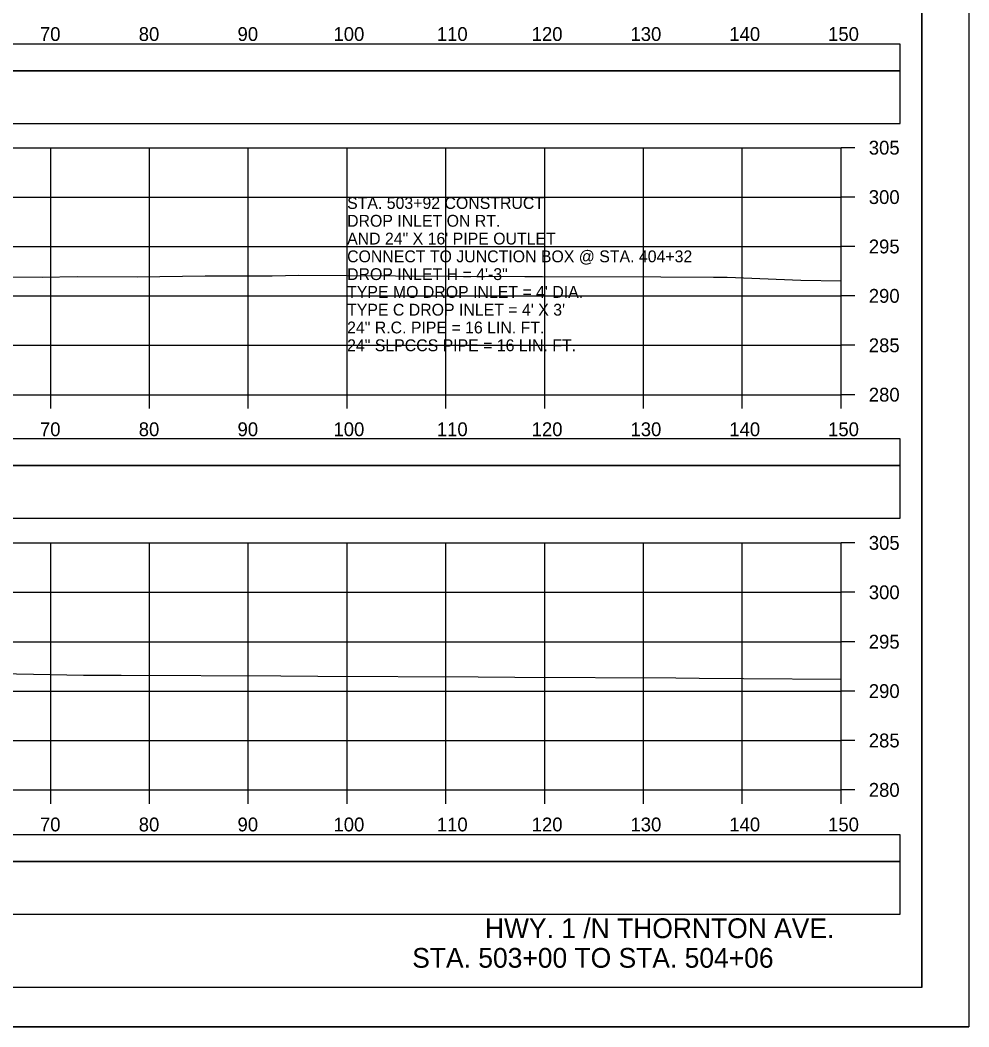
# Model space of a CAD drawing. Extents: x 1370538 to 1372872, y 376220 to 381127.
# Drawn here: x 1372775.6 to 1372871.6, y 376860.4 to 376962.3 of the extents above; entities that cross this region are included whole.
import ezdxf

# ---------------------------------------------------------------- set-up
doc = ezdxf.new("R2010")
doc.units = 0
for name, color, linetype in [('R_Border Notes', 7, 'Continuous'), ('R_Border PE', 7, 'Continuous'), ('R_Border Prem', 7, 'Continuous'), ('R_Dimension', 7, 'Continuous'), ('R_Grid', 7, 'Continuous'), ('R_No Plot', 7, 'Continuous'), ('R_Proposed Road', 7, 'Continuous'), ('R_Water Annot', 7, 'Continuous'), ('T_Detection Zones', 7, 'Continuous')]:
    doc.layers.add(name, color=color, linetype=linetype)

msp = doc.modelspace()

# ---------------------------------------------------------------- linework, layer by layer
at = {"layer": 'R_Border Notes'}
for q in [(1372866.83, 377069.89), (1372550.65, 376864.43)]:
    msp.add_line((1372866.83, 376864.43), q, dxfattribs=at)
at = {"layer": 'R_Border Prem'}
for p, q in [((1372858.65, 376924.43), (1372858.65, 376949.43)), ((1372860.05, 376949.43), (1372858.65, 376949.43)), ((1372860.05, 376944.43), (1372858.65, 376944.43)), ((1372860.05, 376939.43), (1372858.65, 376939.43)), ((1372860.05, 376934.43), (1372858.65, 376934.43)), ((1372860.05, 376929.43), (1372858.65, 376929.43)), ((1372558.65, 376924.43), (1372858.65, 376924.43)), ((1372778.65, 376923.03), (1372778.65, 376924.43)), ((1372788.65, 376923.03), (1372788.65, 376924.43)), ((1372798.65, 376923.03), (1372798.65, 376924.43)), ((1372808.65, 376923.03), (1372808.65, 376924.43)), ((1372818.65, 376923.03), (1372818.65, 376924.43)), ((1372828.65, 376923.03), (1372828.65, 376924.43)), ((1372838.65, 376923.03), (1372838.65, 376924.43)), ((1372848.65, 376923.03), (1372848.65, 376924.43)), ((1372858.65, 376923.03), (1372858.65, 376924.43)), ((1372860.05, 376924.43), (1372858.65, 376924.43)), ((1372858.65, 376884.43), (1372858.65, 376909.43)), ((1372860.05, 376909.43), (1372858.65, 376909.43)), ((1372860.05, 376904.43), (1372858.65, 376904.43)), ((1372860.05, 376899.43), (1372858.65, 376899.43)), ((1372860.05, 376894.43), (1372858.65, 376894.43)), ((1372860.05, 376889.43), (1372858.65, 376889.43)), ((1372558.65, 376884.43), (1372858.65, 376884.43)), ((1372778.65, 376883.03), (1372778.65, 376884.43)), ((1372788.65, 376883.03), (1372788.65, 376884.43)), ((1372798.65, 376883.03), (1372798.65, 376884.43)), ((1372808.65, 376883.03), (1372808.65, 376884.43)), ((1372818.65, 376883.03), (1372818.65, 376884.43)), ((1372828.65, 376883.03), (1372828.65, 376884.43)), ((1372838.65, 376883.03), (1372838.65, 376884.43)), ((1372848.65, 376883.03), (1372848.65, 376884.43)), ((1372858.65, 376883.03), (1372858.65, 376884.43)), ((1372860.05, 376884.43), (1372858.65, 376884.43))]:
    msp.add_line(p, q, dxfattribs=at)
at = {"layer": 'R_Dimension'}
for points in [[(1372772.46, 376936.36), (1372777.79, 376936.33), (1372781.32, 376936.38), (1372787.39, 376936.35), (1372794.29, 376936.45), (1372795.46, 376936.46), (1372801.08, 376936.45), (1372803.77, 376936.53), (1372813.54, 376936.45), (1372819, 376936.44), (1372826.64, 376936.39), (1372827.63, 376936.39), (1372828.44, 376936.39), (1372840.41, 376936.37), (1372845.73, 376936.33), (1372847.1, 376936.31), (1372854.58, 376936.02), (1372858.65, 376935.96)], [(1372770.1, 376896.28), (1372781.97, 376896.05), (1372785.77, 376896.03), (1372801.95, 376895.96), (1372805.7, 376895.94), (1372821.93, 376895.87), (1372825.64, 376895.85), (1372841.91, 376895.78), (1372844.29, 376895.74), (1372848.77, 376895.69), (1372858.65, 376895.65)]]:
    msp.add_lwpolyline(points, dxfattribs=at)
at = {"layer": 'R_Grid'}
for p, q in [((1372558.65, 376949.43), (1372858.65, 376949.43)), ((1372778.65, 376924.43), (1372778.65, 376949.43)), ((1372788.65, 376924.43), (1372788.65, 376949.43)), ((1372798.65, 376924.43), (1372798.65, 376949.43)), ((1372808.65, 376924.43), (1372808.65, 376949.43)), ((1372818.65, 376924.43), (1372818.65, 376949.43)), ((1372828.65, 376924.43), (1372828.65, 376949.43)), ((1372838.65, 376924.43), (1372838.65, 376949.43)), ((1372848.65, 376924.43), (1372848.65, 376949.43)), ((1372858.65, 376924.43), (1372858.65, 376949.43)), ((1372558.65, 376944.43), (1372858.65, 376944.43)), ((1372558.65, 376939.43), (1372858.65, 376939.43)), ((1372558.65, 376934.43), (1372858.65, 376934.43)), ((1372558.65, 376929.43), (1372858.65, 376929.43)), ((1372558.65, 376924.43), (1372858.65, 376924.43)), ((1372558.65, 376909.43), (1372858.65, 376909.43)), ((1372778.65, 376884.43), (1372778.65, 376909.43)), ((1372788.65, 376884.43), (1372788.65, 376909.43)), ((1372798.65, 376884.43), (1372798.65, 376909.43)), ((1372808.65, 376884.43), (1372808.65, 376909.43)), ((1372818.65, 376884.43), (1372818.65, 376909.43)), ((1372828.65, 376884.43), (1372828.65, 376909.43)), ((1372838.65, 376884.43), (1372838.65, 376909.43)), ((1372848.65, 376884.43), (1372848.65, 376909.43)), ((1372858.65, 376884.43), (1372858.65, 376909.43)), ((1372558.65, 376904.43), (1372858.65, 376904.43)), ((1372558.65, 376899.43), (1372858.65, 376899.43)), ((1372558.65, 376894.43), (1372858.65, 376894.43)), ((1372558.65, 376889.43), (1372858.65, 376889.43)), ((1372558.65, 376884.43), (1372858.65, 376884.43))]:
    msp.add_line(p, q, dxfattribs=at)
at = {"layer": 'R_No Plot'}
msp.add_line((1372538.25, 376860.45), (1372871.58, 376860.45), dxfattribs=at)
for points in [[(1372538.24, 377073.78), (1372871.58, 377073.78), (1372871.58, 376860.45), (1372538.24, 376860.45)], [(1372784.57, 377069.89), (1372784.57, 377060.01), (1372820.3, 377060.01), (1372820.3, 377057.09), (1372843.5, 377057.09), (1372843.5, 377032.76), (1372866.83, 377032.76), (1372866.83, 376864.43), (1372550.65, 376864.43), (1372550.65, 377069.89)]]:
    msp.add_lwpolyline(points, close=True, dxfattribs=at)
at = {"layer": 'T_Detection Zones'}
for points in [[(1372552.66, 376957.21), (1372864.63, 376957.21), (1372864.63, 376959.92), (1372552.66, 376959.92)], [(1372552.66, 376951.89), (1372864.63, 376951.89), (1372864.63, 376957.21), (1372552.66, 376957.21)], [(1372552.66, 376917.25), (1372864.63, 376917.25), (1372864.63, 376919.95), (1372552.66, 376919.95)], [(1372552.66, 376911.92), (1372864.63, 376911.92), (1372864.63, 376917.25), (1372552.66, 376917.25)], [(1372552.66, 376877.18), (1372864.63, 376877.18), (1372864.63, 376879.88), (1372552.66, 376879.88)], [(1372552.66, 376871.85), (1372864.63, 376871.85), (1372864.63, 376877.18), (1372552.66, 376877.18)]]:
    msp.add_lwpolyline(points, close=True, dxfattribs=at)

# ---------------------------------------------------------------- texts
at = {"layer": 'R_Border PE'}
for s, p in [('70', (1372777.56, 376960.23)), ('80', (1372787.56, 376960.23)), ('90', (1372797.56, 376960.23)), ('100', (1372807.27, 376960.23)), ('110', (1372817.73, 376960.23)), ('120', (1372827.33, 376960.23)), ('130', (1372837.33, 376960.23)), ('140', (1372847.33, 376960.23)), ('150', (1372857.33, 376960.23)), ('305', (1372861.45, 376948.73)), ('300', (1372861.45, 376943.73)), ('295', (1372861.45, 376938.73)), ('290', (1372861.45, 376933.73)), ('285', (1372861.45, 376928.73)), ('280', (1372861.45, 376923.73)), ('70', (1372777.56, 376920.23)), ('80', (1372787.56, 376920.23)), ('90', (1372797.56, 376920.23)), ('100', (1372807.27, 376920.23)), ('110', (1372817.73, 376920.23)), ('120', (1372827.33, 376920.23)), ('130', (1372837.33, 376920.23)), ('140', (1372847.33, 376920.23)), ('150', (1372857.33, 376920.23)), ('305', (1372861.45, 376908.73)), ('300', (1372861.45, 376903.73)), ('295', (1372861.45, 376898.73)), ('290', (1372861.45, 376893.73)), ('285', (1372861.45, 376888.73)), ('280', (1372861.45, 376883.73)), ('70', (1372777.56, 376880.23)), ('80', (1372787.56, 376880.23)), ('90', (1372797.56, 376880.23)), ('100', (1372807.27, 376880.23)), ('110', (1372817.73, 376880.23)), ('120', (1372827.33, 376880.23)), ('130', (1372837.33, 376880.23)), ('140', (1372847.33, 376880.23)), ('150', (1372857.33, 376880.23))]:
    msp.add_text(s, height=1.4, dxfattribs=at).set_placement(p)
at = {"layer": 'R_Proposed Road'}
for s, p in [('HWY. 1 /N THORNTON AVE.', (1372822.6, 376869.43)), ('STA. 503+00 TO STA. 504+06', (1372815.24, 376866.43))]:
    msp.add_text(s, height=2, dxfattribs=at).set_placement(p)
at = {"layer": 'R_Water Annot'}
for s, p in [('STA. 503+92 CONSTRUCT', (1372808.65, 376943.23)), ('DROP INLET ON RT.', (1372808.65, 376941.43)), ('AND 24" X 16\' PIPE OUTLET', (1372808.65, 376939.63)), ('CONNECT TO JUNCTION BOX @ STA. 404+32', (1372808.65, 376937.83)), ('DROP INLET H = 4\'-3"', (1372808.65, 376936.03)), ("TYPE MO DROP INLET = 4' DIA.", (1372808.65, 376934.23)), ("TYPE C DROP INLET = 4' X 3'", (1372808.65, 376932.43)), ('24" R.C. PIPE = 16 LIN. FT.', (1372808.65, 376930.63)), ('24" SLPCCS PIPE = 16 LIN. FT.', (1372808.65, 376928.83))]:
    msp.add_text(s, height=1.2, dxfattribs=at).set_placement(p)

doc.saveas('drawing.dxf')
